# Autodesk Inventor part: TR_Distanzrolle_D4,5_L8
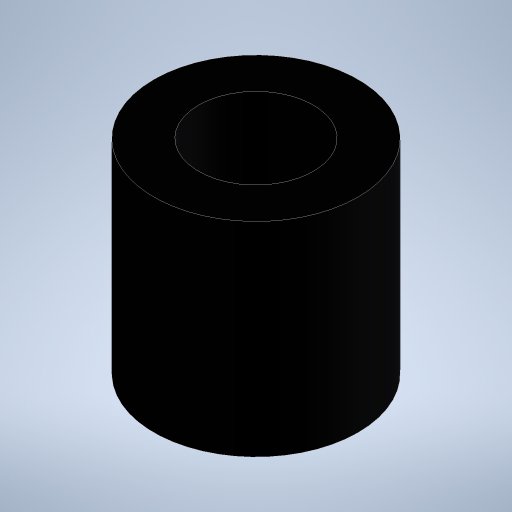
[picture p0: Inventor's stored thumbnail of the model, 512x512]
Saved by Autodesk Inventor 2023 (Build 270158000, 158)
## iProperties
Created: 2023-11
Part Number: TR_Distanzrolle_D4,5_L8
Material: PC/ABS-Kunststoff
Document SubType Name: Modeling
Designer: Admin
Density: 0.357273 g/cm^3
Appearance: Glatt - Schwarz
Author: Admin
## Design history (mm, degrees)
sketch "Skizze1"
  geometry: C1 r 2.25 at (0, 0); C2 r 4 at (0, 0); 1 further point
  constraints: 2 centre point, 2 coincident
  dimensions: "d0" = 4.5 diameter of C1; "d1" = 8 diameter of C2
extrude "Extrusion1" new body sketch "Skizze1" distance "d2" = 8; taper "d3" = 0 deg
node "Volumenkörper1"
